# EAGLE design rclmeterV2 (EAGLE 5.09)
TP_SIGNAL_NAME: DUT-
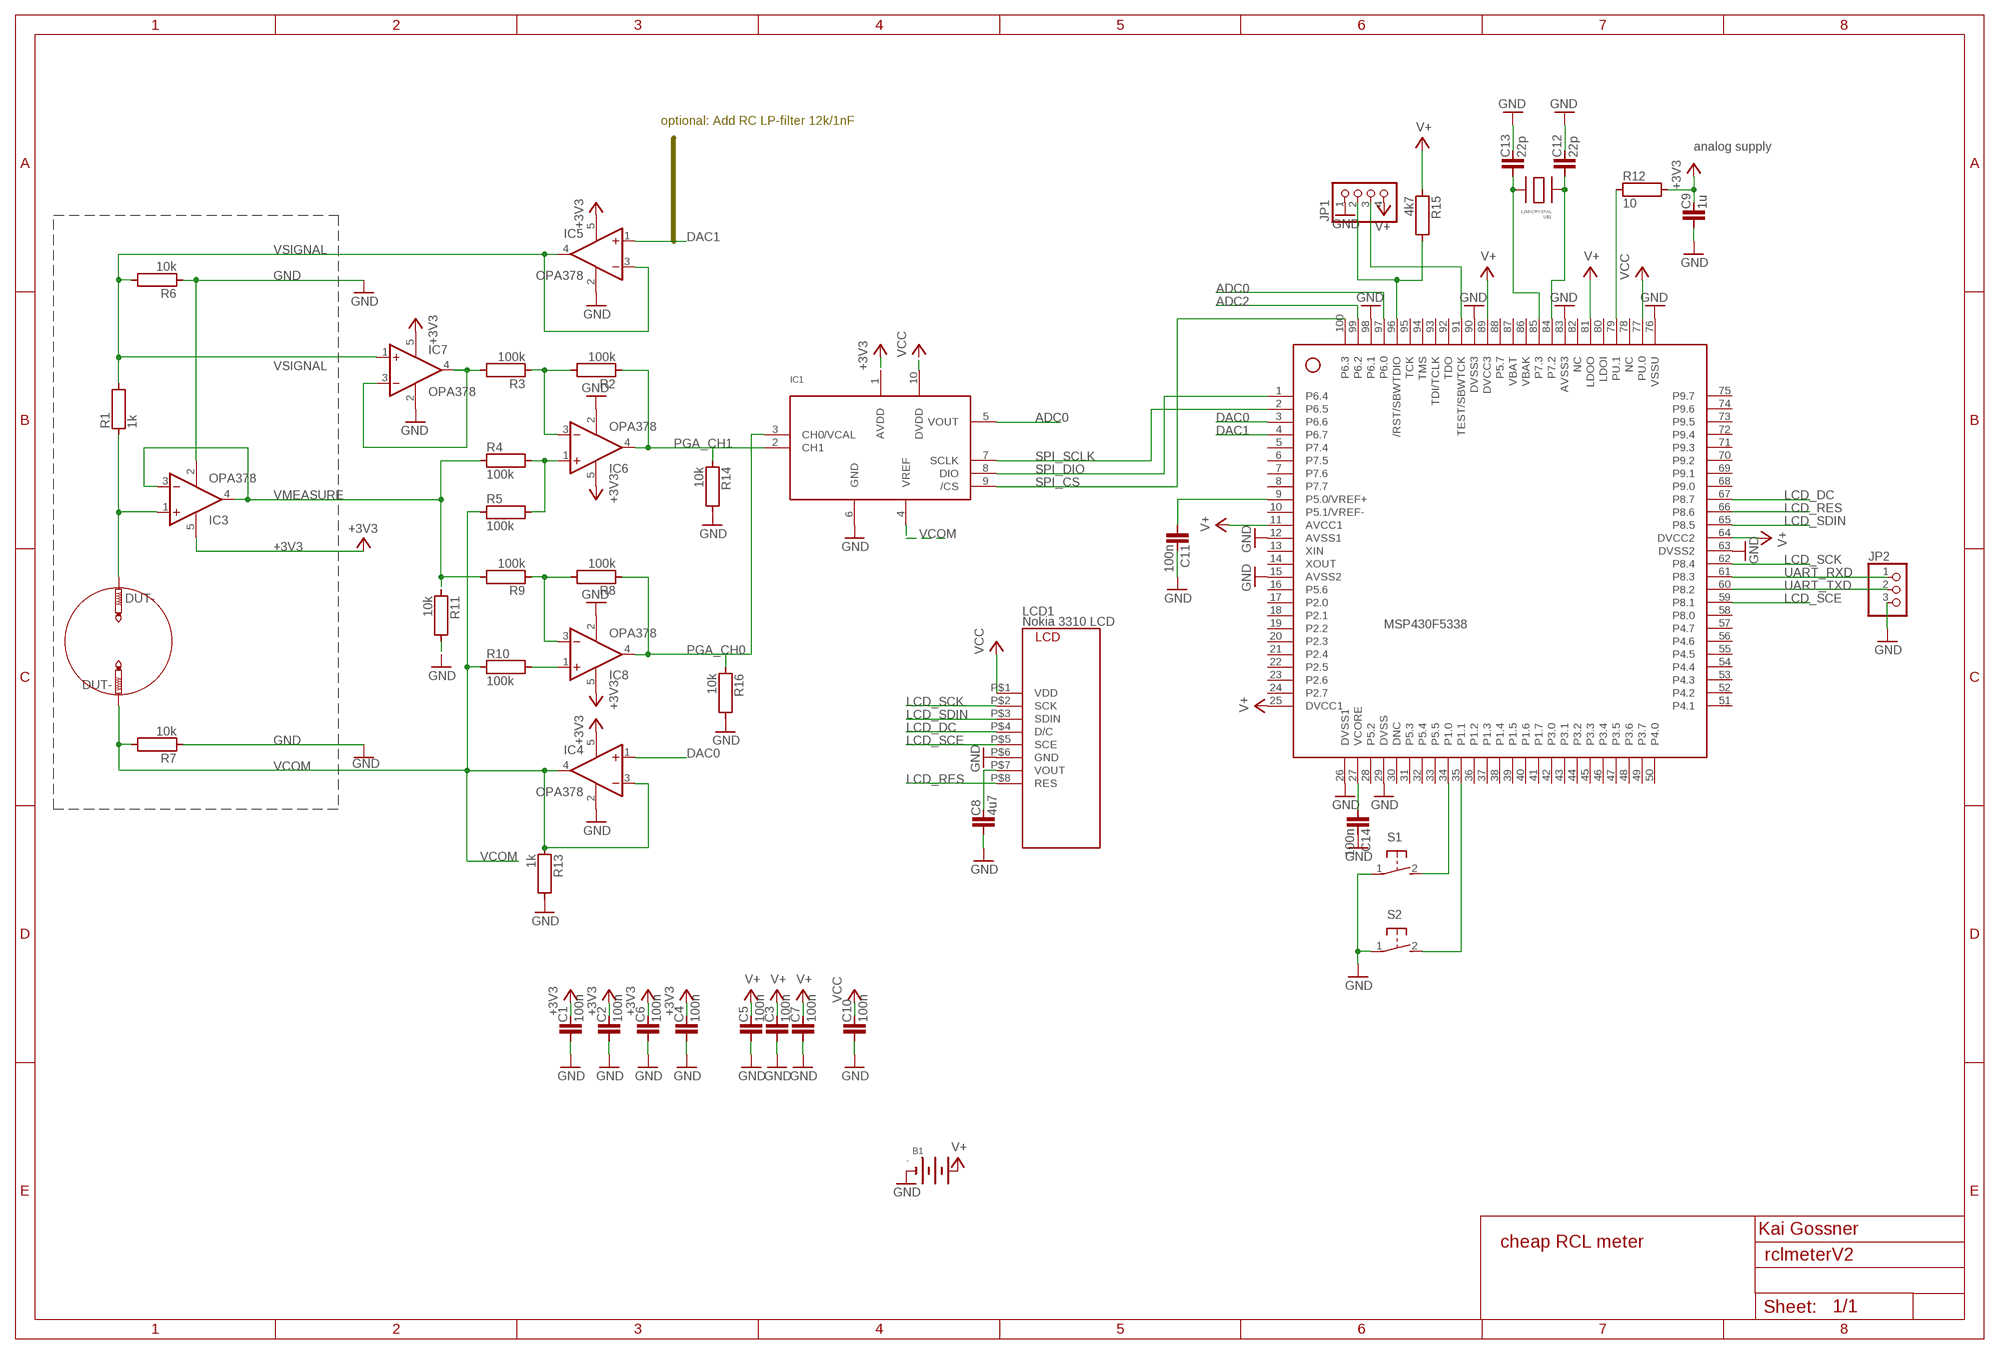
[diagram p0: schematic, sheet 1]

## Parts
B1  BATTERYCR2032  [CR2032]
C1  100n  C0603  [C0603]
C2  100n  C0603  [C0603]
C3  100n  C0603  [C0603]
C4  100n  C0603  [C0603]
C5  100n  C0603  [C0603]
C6  100n  C0603  [C0603]
C7  100n  C0603  [C0603]
C8  4u7  C0805  [C0805]
C9  1u  C0805  [C0805]
C10  100n  C0603  [C0603]
C11  100n  C0603  [C0603]
C12  22p  C0603  [C0603]
C13  22p  C0603  [C0603]
C14  100n  C0603  [C0603]
IC1  PGA113  [MSOP10_NO_TP]
IC2  F5338  [PZ100]
IC3  OPA378  [DCK_R-PDSO-G5]
IC4  OPA378  [DCK_R-PDSO-G5]
IC5  OPA378  [DCK_R-PDSO-G5]
IC6  OPA378  [DCK_R-PDSO-G5]
IC7  OPA378  [DCK_R-PDSO-G5]
IC8  OPA378  [DCK_R-PDSO-G5]
JP1  PINHD-1X4  [1X04]
JP2  PINHD-1X3  [1X03]
LCD1  NOKIA3310  [NOKIALCD]
R1  1k  R0603  [R0603]
R2  100k  R0603  [R0603]
R3  100k  R0603  [R0603]
R4  100k  R0603  [R0603]
R5  100k  R0603  [R0603]
R6  10k  R0603  [R0603]
R7  10k  R0603  [R0603]
R8  100k  R0603  [R0603]
R9  100k  R0603  [R0603]
R10  100k  R0603  [R0603]
R11  10k  R0603  [R0603]
R12  10  R0603  [R0603]
R13  1k  R0603  [R0603]
R14  10k  R0603  [R0603]
R15  4k7  R0603  [R0603]
R16  10k  R0603  [R0603]
S1  31-XX  [B3F-31XX]
S2  31-XX  [B3F-31XX]
TP1  DUT+  PTR1  [B0.6]
TP2  PTR1  [B0.6]
U$1  12M-CRYSTAL  7M-CRYSTAL  [XTAL3.2X2.5]

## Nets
+3V3: C1.2 C2.2 C4.2 C6.2 C9.2 IC1.1(AVDD) IC3.5(V+) IC4.5(V+) IC5.5(V+) IC6.5(V+) IC7.5(V+) IC8.5(V+) R12.2
ADC0: IC1.5(VOUT) IC2.97(P6.0)
ADC2: IC2.99(P6.2)
DAC0: IC2.3(P6.6) IC4.1(+IN)
DAC1: IC2.4(P6.7) IC5.1(+IN)
GND: B1.- C1.1 C2.1 C3.1 C4.1 C5.1 C6.1 C7.1 C8.1 C9.1 C10.1 C11.2 C12.2 C13.2 C14.2 IC1.6(GND) IC2.12(AVSS1) IC2.15(AVSS2) IC2.26(DVSS1) IC2.29(DVSS) IC2.63(DVSS2) IC2.76(VSSU) IC2.83(AVSS3) IC2.90(DVSS3) IC2.98(P6.1) IC3.2(V-) IC4.2(V-) IC5.2(V-) IC6.2(V-) IC7.2(V-) IC8.2(V-) JP1.1 JP2.3 LCD1.P$6(GND) R6.1 R7.1 R11.2 R13.2 R14.2 R16.2 S1.1(P) S2.1(P)
LCD_DC: IC2.67(P8.7) LCD1.P$4(D/C)
LCD_RES: IC2.66(P8.6) LCD1.P$8(RES)
LCD_SCE: IC2.59(P8.1) LCD1.P$5(SCE)
LCD_SCK: IC2.62(P8.4) LCD1.P$2(SCK)
LCD_SDIN: IC2.65(P8.5) LCD1.P$3(SDIN)
N$2: IC7.3(-IN) IC7.4(OUT) R3.2
N$3: C12.1 IC2.84(P7.2) U$1.2
N$4: IC3.1(+IN) R1.1 TP1.TP
N$5: C13.1 IC2.85(P7.3) U$1.4
N$6: IC8.1(+IN) R10.2
N$7: IC6.1(+IN) R4.2 R5.2
N$8: IC6.3(-IN) R2.2 R3.1
N$10: IC8.3(-IN) R8.2 R9.1
N$11: IC2.79(PU.1) R12.1
N$12: C11.1 IC2.9(P5.0/VREF+)
N$13: C8.2 LCD1.P$7(VOUT)
N$14: IC2.34(P1.0) S1.2(S)
N$15: IC2.35(P1.1) S2.2(S)
N$16: IC2.96(/RST/SBWTDIO) JP1.2 R15.2
N$17: IC2.91(TEST/SBWTCK) JP1.3
N$19: C14.1 IC2.27(VCORE)
PGA_CH0: IC1.3(CH0/VCAL) IC8.4(OUT) R8.1 R16.1
PGA_CH1: IC1.2(CH1) IC6.4(OUT) R2.1 R14.1
SPI_CS: IC1.9(/CS) IC2.100(P6.3)
SPI_DIO: IC1.8(DIO) IC2.1(P6.4)
SPI_SCLK: IC1.7(SCLK) IC2.2(P6.5)
UART_RXD: IC2.61(P8.3) JP2.1
UART_TXD: IC2.60(P8.2) JP2.2
V+: B1.+ C3.2 C5.2 C7.2 IC2.11(AVCC1) IC2.25(DVCC1) IC2.64(DVCC2) IC2.81(LDOO) IC2.89(DVCC3) JP1.4 R15.1
VCC: C10.2 IC1.10(DVDD) IC2.77(PU.0) LCD1.P$1(VDD)
VCOM: IC1.4(VREF) IC4.3(-IN) IC4.4(OUT) R5.1 R7.2 R10.1 R13.1 TP2.TP
VMEASURE: IC3.3(-IN) IC3.4(OUT) R4.1 R9.2 R11.1
VSIGNAL: IC5.3(-IN) IC5.4(OUT) IC7.1(+IN) R1.2 R6.2
Unconnected: IC2.5(P7.4) IC2.6(P7.5) IC2.7(P7.6) IC2.8(P7.7) IC2.10(P5.1/VREF-) IC2.13(XIN) IC2.14(XOUT) IC2.16(P5.6) IC2.17(P2.0) IC2.18(P2.1) IC2.19(P2.2) IC2.20(P2.3) IC2.21(P2.4) IC2.22(P2.5) IC2.23(P2.6) IC2.24(P2.7) IC2.28(P5.2) IC2.30(DNC) IC2.31(P5.3) IC2.32(P5.4) IC2.33(P5.5) IC2.36(P1.2) IC2.37(P1.3) IC2.38(P1.4) IC2.39(P1.5) IC2.40(P1.6) IC2.41(P1.7) IC2.42(P3.0) IC2.43(P3.1) IC2.44(P3.2) IC2.45(P3.3) IC2.46(P3.4) IC2.47(P3.5) IC2.48(P3.6) IC2.49(P3.7) IC2.50(P4.0) IC2.51(P4.1) IC2.52(P4.2) IC2.53(P4.3) IC2.54(P4.4) IC2.55(P4.5) IC2.56(P4.6) IC2.57(P4.7) IC2.58(P8.0) IC2.68(P9.0) IC2.69(P9.1) IC2.70(P9.2) IC2.71(P9.3) IC2.72(P9.4) IC2.73(P9.5) IC2.74(P9.6) IC2.75(P9.7) IC2.78(NC) IC2.80(LDOI) IC2.82(NC) IC2.86(VBAK) IC2.87(VBAT) IC2.88(P5.7) IC2.92(TDO) IC2.93(TDI/TCLK) IC2.94(TMS) IC2.95(TCK)

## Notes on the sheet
- optional: Add RC LP-filter 12k/1nF
- analog supply
- Nokia 3310 LCD | MSP430F5338
- Kai Gossner
- cheap RCL meter

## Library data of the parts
B1 = microbuilder:BATTERY
C1-C14 = KaiLib:C
IC1 = texas:PGA113
IC2 = TI_MSP430_v16:F5338
IC3-IC8 = texas:OPA378
JP1 = pinhead:PINHD-1X4: PIN HEADER
JP2 = pinhead:PINHD-1X3: PIN HEADER
LCD1 = KaiLib:NOKIA3310
R1-R16 = KaiLib:R
S1 S2 = switch-omron:31-XX: OMRON SWITCH
TP1 TP2 = testpad:PTR1: TEST PIN
U$1 = kg:7M-CRYSTAL

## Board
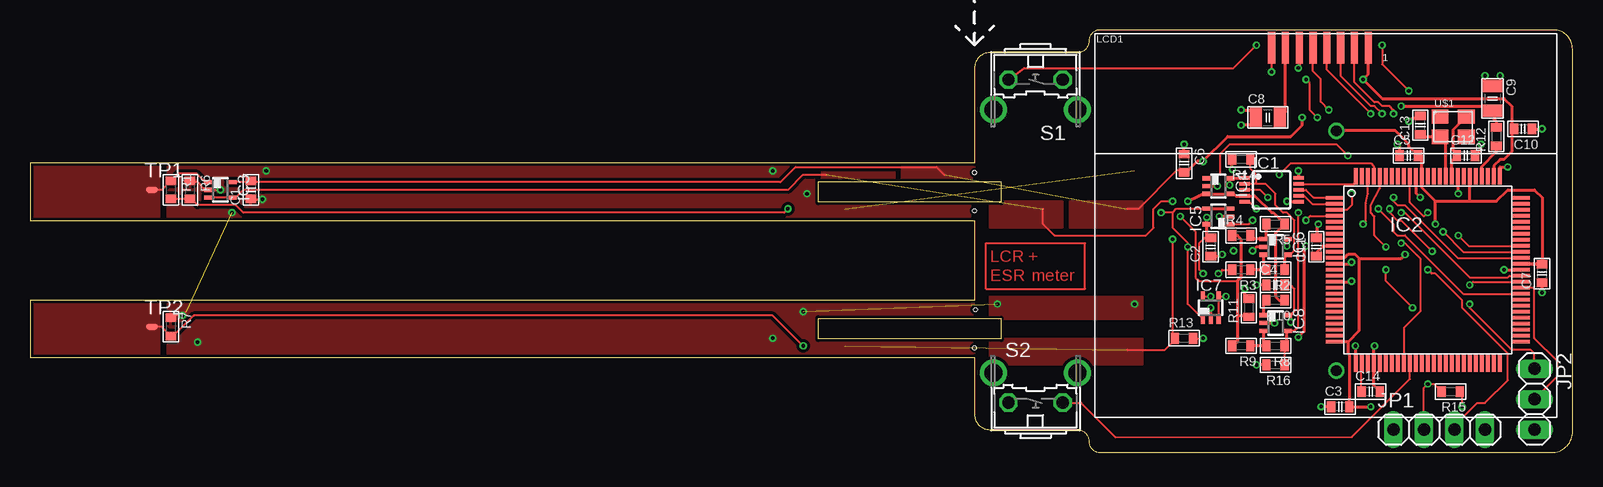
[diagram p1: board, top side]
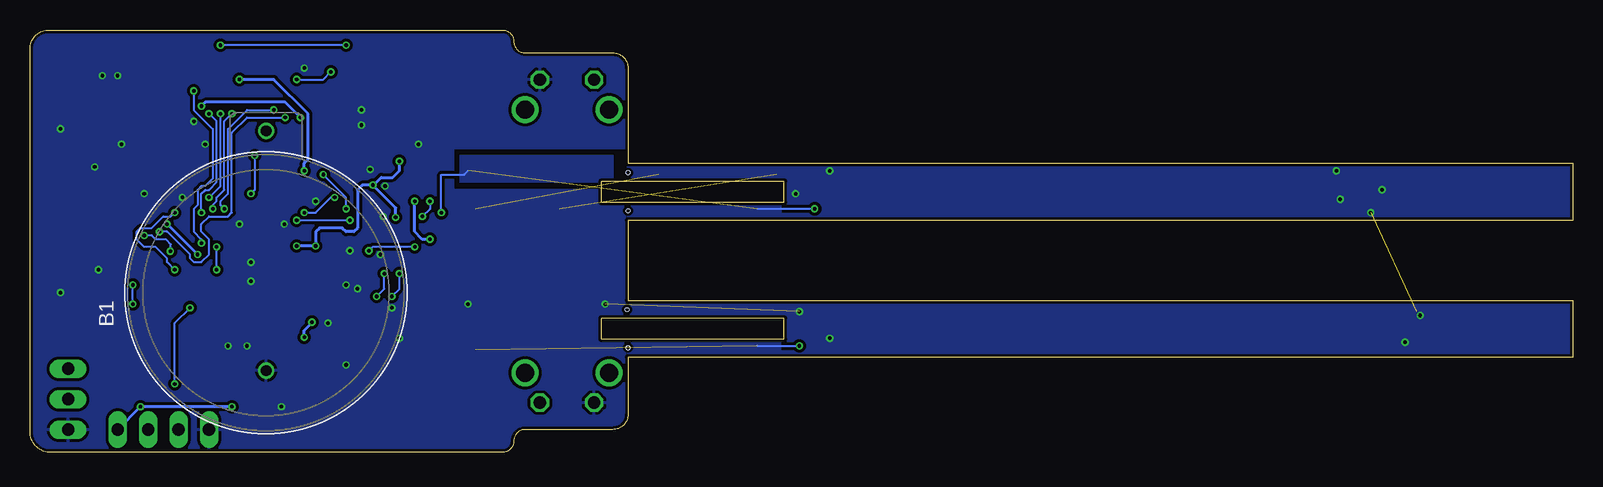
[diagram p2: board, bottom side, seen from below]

Size 128.59 x 35.25 mm. Coordinates in mm from the lower left corner, seen from the top.
Outline: 128.59,33.66 arc90 127,35.25 89.22,35.25 arc90 88.27,34.3 arc-90 87.31,33.34 80.01,33.34 arc90 78.74,32.07 78.74,24.14 0,24.14 0,19.37 78.74,19.37 78.74,12.71 0,12.71 0,7.94 78.74,7.94 78.74,3.18 arc90 80.01,1.91 87.31,1.91 arc-90 88.27,0.96 arc90 89.22,0.01 126.68,0.01 arc90 128.59,1.59 128.59,33.66
Outline: 65.72,20.89 65.72,22.62 80.96,22.62 80.96,20.89 65.72,20.89
Outline: 65.72,9.46 65.72,11.19 80.96,11.19 80.96,9.46 65.72,9.46
Copper layers (1*16): Top 0.035mm / dielectric 1.5mm / Bottom 0.035mm
Design rules "default *": minimum track width 5.5mil, minimum drill 0.25mm, track to track 5.5mil, track to pad 5.5mil, pad to pad 5.5mil, via to via 5.5mil, smd to smd 1mil, copper to edge 8mil, drill to drill 8mil, minimum pad ring 0.15mm, minimum via ring 0.15mm, stop-mask expansion 4mil, vias tented up to drill 0.35mm, thermal gap 10mil
Holes 0.3 mm at 78.74,23.34 78.82,11.91 78.74,20.17 78.74,8.74
tRestrict: 1 lines

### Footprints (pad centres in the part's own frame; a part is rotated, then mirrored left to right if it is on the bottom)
CR2032 = drill 0.9 round: + 10,0; - -10,0
C0603 = smd 0.7 x 0.9: 1 -0.762,0; 2 0.762,0
C0805 = smd 1 x 1.7: 1 -1.016,0; 2 1.016,0
MSOP10_NO_TP = smd 0.32 x 0.9: 1 -1,-2.25; 2 -0.5,-2.25; 3 0,-2.25; 4 0.5,-2.25; 5 1,-2.25; 6 1,2.25; 7 0.5,2.25; 8 0,2.25; 9 -0.5,2.25; 10 -1,2.25
PZ100 = smd 1.4 x 0.3: 1 -7.8,6; 2 -7.8,5.5; 3 -7.8,5; 4 -7.8,4.5; 5 -7.8,4; 6 -7.8,3.5; 7 -7.8,3; 8 -7.8,2.5; 9 -7.8,2; 10 -7.8,1.5; 11 -7.8,1; 12 -7.8,0.5; 13 -7.8,0; 14 -7.8,-0.5; 15 -7.8,-1; 16 -7.8,-1.5; 17 -7.8,-2; 18 -7.8,-2.5; 19 -7.8,-3; 20 -7.8,-3.5; 21 -7.8,-4; 22 -7.8,-4.5; 23 -7.8,-5; 24 -7.8,-5.5; 25 -7.8,-6; 51 7.8,-6; 52 7.8,-5.5; 53 7.8,-5; 54 7.8,-4.5; 55 7.8,-4; 56 7.8,-3.5; 57 7.8,-3; 58 7.8,-2.5; 59 7.8,-2; 60 7.8,-1.5; 61 7.8,-1; 62 7.8,-0.5; 63 7.8,0; 64 7.8,0.5; 65 7.8,1; 66 7.8,1.5; 67 7.8,2; 68 7.8,2.5; 69 7.8,3; 70 7.8,3.5; 71 7.8,4; 72 7.8,4.5; 73 7.8,5; 74 7.8,5.5; 75 7.8,6 | smd 0.3 x 1.4: 26 -6,-7.8; 27 -5.5,-7.8; 28 -5,-7.8; 29 -4.5,-7.8; 30 -4,-7.8; 31 -3.5,-7.8; 32 -3,-7.8; 33 -2.5,-7.8; 34 -2,-7.8; 35 -1.5,-7.8; 36 -1,-7.8; 37 -0.5,-7.8; 38 0,-7.8; 39 0.5,-7.8; 40 1,-7.8; 41 1.5,-7.8; 42 2,-7.8; 43 2.5,-7.8; 44 3,-7.8; 45 3.5,-7.8; 46 4,-7.8; 47 4.5,-7.8; 48 5,-7.8; 49 5.5,-7.8; 50 6,-7.8; 76 6,7.8; 77 5.5,7.8; 78 5,7.8; 79 4.5,7.8; 80 4,7.8; 81 3.5,7.8; 82 3,7.8; 83 2.5,7.8; 84 2,7.8; 85 1.5,7.8; 86 1,7.8; 87 0.5,7.8; 88 0,7.8; 89 -0.5,7.8; 90 -1,7.8; 91 -1.5,7.8; 92 -2,7.8; 93 -2.5,7.8; 94 -3,7.8; 95 -3.5,7.8; 96 -4,7.8; 97 -4.5,7.8; 98 -5,7.8; 99 -5.5,7.8; 100 -6,7.8
DCK_R-PDSO-G5 = smd 0.35 x 0.8: 1 -0.65,-0.95; 2 0,-0.95; 3 0.65,-0.95; 4 0.65,0.95; 5 -0.65,0.95
1X04 = drill 1.016 long: 1 -3.81,0; 2 -1.27,0; 3 1.27,0; 4 3.81,0
1X03 = drill 1.016 long: 1 -2.54,0; 2 0,0; 3 2.54,0
NOKIALCD = smd 0.6 x 2.65: P$1 8.05,-1.15; P$2 6.9,-1.15; P$3 5.75,-1.15; P$4 4.6,-1.15; P$5 3.45,-1.15; P$6 2.3,-1.15; P$7 1.15,-1.15; P$8 0,-1.15
R0603 = smd 0.7 x 0.9: 1 -0.762,0; 2 0.762,0
B3F-31XX = drill 1.016 octagon: 1 -2.261,-1.245; 2 2.261,-1.245 | drill 1.499 pad 2.159 round: 3 -3.505,1.245; 4 3.505,1.245
B0.6 = smd 1.016 x 0.508: TP 0,0
XTAL3.2X2.5 = smd 1.4 x 1.2: 1 0.7,2.3; 2 2.9,2.3; 3 2.9,0.6; 4 0.7,0.6

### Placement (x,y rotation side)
B1  108.9,16.83 90 bottom
C1  18.41,21.91 90 top
C2  98.42,17.15 90 top
C3  109.22,3.82 0 top
C4  103.82,13.98 0 top
C5  114.94,24.77 0 top
C6  96.2,24.14 270 top
C7  126.05,14.93 90 top
C8  103.19,27.95 0 top
C9  121.92,29.53 270 top
C10  124.46,26.99 180 top
C11  107.24,17.15 90 top
C12  119.7,24.77 0 top
C13  115.89,27.31 90 top
C14  111.76,5.09 0 top
IC1  103.5,21.91 270 top
IC2  116.52,15.25 0 top
IC3  15.88,21.91 270 top
IC4  99.06,22.23 270 top
IC5  99.06,19.69 90 top
IC6  103.82,17.15 270 top
IC7  98.42,12.07 0 top
IC8  103.82,10.8 270 top
JP1  117.47,1.91 0 top
JP2  125.41,4.45 270 top
LCD1  103.5,34.93 0 top
R1  11.75,21.91 270 top
R2  103.82,15.25 180 top
R3  100.97,15.25 180 top
R4  100.97,18.1 0 top
R5  103.82,19.06 180 top
R6  13.34,21.91 270 top
R7  11.75,10.48 270 top
R8  103.82,8.9 180 top
R9  100.97,8.9 180 top
R10  103.82,12.71 180 top
R11  101.6,12.07 90 top
R12  122.24,26.36 90 top
R13  96.2,9.53 0 top
R14  100.97,24.45 180 top
R15  118.43,5.09 180 top
R16  103.82,7.31 180 top
S1  83.82,29.85 180 top
S2  83.82,5.4 0 top
TP1  10.16,21.91 0 top
TP2  10.16,10.48 0 top
U$1  116.84,25.72 0 top

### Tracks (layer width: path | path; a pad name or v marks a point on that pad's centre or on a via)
+3V3  (via drill 0.3)  (1 unrouted)
  Top 0.155: IC3.5 17.13,22.56 17.14,22.55 18.41,22.55 | 104.47,11.45 IC8.5 105.11,11.45 105.41,11.75 105.41,13.66 105.09,13.98 C4.2 | 18.41,22.55 62.55,22.55 63.82,23.82 75.56,23.82 76.2,23.18 | 18.41,22.55 C1.2 | C6.2 96.2,23.5 95.57,23.5 92.39,20.33 91.44,20.33 | C2.2 97.92,17.91 97.47,17.47 97.47,15.25 v97.79,14.93 | v98.42,13.02 IC7.5
  Top 0.254: 105.11,11.45 105.09,11.44 v105.09,10.88 | IC1.1 101.22,22.88 IC4.5 v100.01,22.31 | v98.11,19.61 98.11,19.69 IC5.5 98.11,18.23 C2.2 | IC6.5 104.77,17.15 v104.78,17.23 | C6.2 96.65,23.63 97.31,24.3 v97.79,24.3 99.85,26.36 105.09,26.36 106.05,27.31 v106.05,27.95 | 122.06,28.18 122.06,27.81 122.24,27.63 R12.2 | 122.06,28.18 121.98,28.65 | v106.36,17.23 106.2,16.91 106.2,10.09 v105.73,9.61 | 122.06,28.18 122.06,28.52 C9.2 121.54,28.9 v114.3,28.9
  Bottom 0.155: v97.79,14.93 97.79,13.66 v98.42,13.02
  Bottom 0.254: v106.36,17.23 v104.78,17.23 104.78,18.42 104.46,18.74 102.55,18.74 102.23,18.42 101.6,18.42 101.28,18.74 101.28,21.91 100.89,22.31 v100.01,22.31 | v105.73,9.61 105.73,10.17 105.09,10.8 v105.09,10.88 | v98.11,19.61 98.11,20.41 v100.01,22.31 | v97.79,24.3 97.79,23.5 98.35,22.95 99.3,22.95 99.69,22.55 99.93,22.31 v100.01,22.31 | v114.3,28.9 113.98,29.22 107.31,29.22 v106.05,27.95
  pour Top (isolate 0.254): 72.71,22.55 72.71,24.14 78.74,24.14 78.74,22.55
  pour Top (isolate 0.254): 86.68,18.74 86.68,20.96 92.71,20.96 92.71,18.74
ADC0  (via drill 0.3)
  Top 0.155: IC1.5 101.65,20.91 v102.23,20.33 | v104.14,23.18 105.09,24.14 111.76,24.14 112.02,23.87 IC2.97
  Bottom 0.155: v102.23,20.33 102.23,21.28 v104.14,23.18
DAC0  (via drill 0.3)
  Top 0.155: IC4.1 98.76,22.88 99.22,23.34 99.22,24.93 100.01,25.72 108.9,25.72 v109.85,24.77 | v110.17,21.6 110.17,20.64 109.78,20.25 IC2.3
  Bottom 0.155: v109.85,24.77 109.85,21.91 v110.17,21.6
DAC1  (via drill 0.3)
  Top 0.155: IC5.1 101.59,19.04 v101.92,19.37 | 106.68,19.69 v106.36,19.37 106.73,19.75 IC2.4
  Bottom 0.155: v101.92,19.37 v106.36,19.37
GND  (via drill 0.3)  (2 unrouted)
  Top 0.155: v15.88,21.91 IC3.2 14.6,21.91 13.97,22.55 13.46,22.55 R6.1 | v19.37,21.12 18.45,21.12 C1.1 | R7.1 11.94,11.44 v12.7,11.44 13.02,11.75 | IC2.98 111.52,21.6 111.36,20.8 111.36,19.3 v111.12,19.06 | R13.2 v97.79,9.53
  Top 0.254: IC4.2 v98.98,22.23 | IC8.2 v103.74,10.8 | IC6.2 102.23,17.15 v101.92,16.83 | IC5.2 v99.14,19.69 | R11.2 101.41,13.02 101.28,13.02 v101.28,13.66 | IC2.90 115.52,21.64 v115.89,21.28 | IC2.83 119.02,21.64 v119.06,21.6 | v122.87,15.25 IC2.63 | IC2.12 110.04,15.75 v110.17,15.88 | IC2.15 110.12,14.25 v110.17,14.29 | IC2.26 110.52,8.86 v110.49,8.9 | v112.08,8.9 112.02,8.84 IC2.29 112.02,5.59 C14.2 | IC1.6 104.82,20.91 v104.78,20.96 | C4.1 v102.23,13.98 | C6.1 96.33,24.96 96.2,25.09 v96.2,25.72 | C2.1 99.25,16.39 v99.38,16.52 | v126.05,13.34 C7.1 | C9.1 122.3,30.55 122.56,30.8 v122.56,31.44 | 121.28,30.8 v121.28,31.44 | LCD1.P$6 105.81,32.15 v105.73,32.07 | C10.1 v126.05,26.99 | C11.2 107.31,18.1 107.31,18.98 v107.39,19.06 | C3.1 v107.63,3.82 | C13.2 115.06,27.76 v114.94,27.63 | C12.2 120.97,25.28 v120.97,25.72 | IC2.76 122.52,23.79 122.56,23.82 v123.19,23.82 | C5.1 114.17,25.53 v113.98,25.72 | IC7.2 v98.42,12.07 | C8.1 102.17,27.31 v100.97,27.31 | v100.97,28.58 101.92,28.58 101.92,27.95 | R14.2 100.2,23.64 v100.23,23.61 | R16.2 v102.23,7.31
  other vias: 64.77,21.6 64.45,11.75 61.91,9.53 13.97,9.21 16.83,20.01 61.91,23.5 19.69,23.5 92.08,12.39 80.64,12.39
  pour Bottom (isolate 0.254): 78.74,35.25 78.74,25.41 93.34,25.41 93.34,21.91 78.74,21.91 78.74,0.32 128.59,0.01 128.59,35.25
  pour Bottom (isolate 0.254): 0,24.3 0,19.37 78.74,19.37 78.74,24.3
  pour Bottom (isolate 0.254): 0,12.71 0,7.94 78.74,7.94 78.74,12.71
  pour Top (isolate 0.254): 11.43,24.14 11.43,19.37 78.74,19.37 78.74,20.96 65.41,20.96 65.41,24.14
  pour Top (isolate 0.254): 11.43,12.71 11.43,7.94 78.74,7.94 78.74,9.53 65.41,9.53 65.41,11.12 78.74,11.12 78.74,12.71
  pour Top: 80.01,11.12 80.01,13.02 92.71,13.02 92.71,11.12
LCD_DC  (via drill 0.3)
  Top 0.155: v116.89,16.79 114.3,19.37 113.98,19.37 113.35,20.01 v113.35,20.33 | v111.76,28.26 108.1,31.92 LCD1.P$4 | IC2.67 119.92,17.25 v119.06,18.1
  Bottom 0.155: v113.35,20.33 113.35,20.64 113.03,20.96 113.03,21.28 112.39,21.91 112.39,27.63 v111.76,28.26 | v116.89,16.79 116.84,16.83 116.84,17.37 117.25,17.79 118.11,17.79 118.43,18.1 v119.06,18.1
LCD_RES  (via drill 0.3)
  Top 0.155: v107.31,27.95 106.68,28.58 106.68,30.8 v106.36,31.12 | v103.5,31.76 LCD1.P$8 | IC2.66 119.47,16.75 v117.79,18.42
  Bottom 0.155: v107.31,27.95 110.49,27.95 111.76,26.68 111.76,20.01 112.08,19.69 113.66,19.69 114.3,19.06 114.3,18.42 113.66,17.79 113.66,16.52 114.3,15.88 114.94,15.88 115.25,16.2 115.25,16.52 117.16,18.42 v117.79,18.42 | v106.36,31.12 104.14,31.12 v103.5,31.76
LCD_SCE  (via drill 0.3)
  Top 0.155: IC2.59 119.47,13.25 114.62,18.1 113.98,18.1 113.66,18.42 113.66,19.06 v112.39,20.33 | v108.27,28.58 107.59,29.26 107.59,31.16 106.95,31.8 LCD1.P$5
  Bottom 0.155: v112.39,20.33 112.71,20.64 112.71,20.96 112.08,21.6 112.08,26.99 110.49,28.58 v108.27,28.58
LCD_SCK  (via drill 0.3)
  Top 0.155: IC2.62 123.33,14.75 123.19,14.61 120.02,14.61 114.62,20.01 v114.3,20.01 | v113.66,28.26 113.66,28.58 113.35,28.9 112.71,28.9 112.39,29.22 112.08,29.22 110.41,30.89 LCD1.P$2
  Bottom 0.155: v114.3,20.01 114.3,21.6 113.98,21.91 113.66,21.91 113.03,22.55 113.03,27.63 v113.66,28.26
LCD_SDIN  (via drill 0.3)
  Top 0.155: IC2.65 119.02,16.25 114.62,20.64 113.98,20.64 113.66,20.96 v113.66,21.28 | v112.71,28.26 112.08,28.9 111.76,28.9 109.25,31.4 LCD1.P$3
  Bottom 0.155: v113.66,21.28 112.71,22.23 v112.71,28.26
N$1
  Top 0.155: 79.69,13.66 79.69,17.47 87.95,17.47 87.95,13.66 79.69,13.66
N$2  (via drill 0.3)
  Top 0.155: IC7.3 IC7.4 v99.69,13.02 | R3.2 99.38,15.25 v99.06,14.93
  Bottom 0.155: v99.06,14.93 99.06,13.66 v99.69,13.02
N$3
  Top 0.254: IC2.84 118.52,24.36 C12.1 118.94,24.9 118.67,25.17 118.67,26.95 U$1.2
N$4
  Top 0.155: TP1.TP 10.99,21.91 R1.1 12.34,23.26 13.89,23.26 14.59,22.56 IC3.1
  pour Top (isolate 0.254, no thermals): 0,24.14 0,19.37 10.8,19.37 10.8,24.14
N$5
  Top 0.254: IC2.85 118.02,25.84 U$1.4 115.98,26.32 C13.1
N$6
  Top 0.254: IC8.1 102.87,12.52 R10.2
N$7
  Top 0.254: R5.2 103.06,17.99 IC6.1 102.06,17.8 R4.2
N$8
  Top 0.254: R3.1 R2.2 102.87,15.44 IC6.3
N$10
  Top 0.254: IC8.3 102.87,9.09 R8.2 R9.1
N$11
  Top 0.254: IC2.79 121.02,23.87 122.24,25.09 122.29,25.54 R12.1
N$12
  Top 0.254: IC2.9 107.81,17.25 107.08,16.52 C11.1
N$13
  Top 0.254: LCD1.P$7 104.66,28.4 C8.2
N$14  (via drill 0.3)
  Top 0.155: v112.71,33.98 112.71,32.39 v114.94,30.17 | v114.3,17.47 114.62,17.47 115.89,16.2 115.89,11.75 114.52,10.39 IC2.34 | v102.23,33.98 100.33,32.07 82.86,32.07 S1.2
  Bottom 0.155: v114.94,30.17 114.94,28.58 113.35,26.99 113.35,22.87 113.98,22.23 114.3,22.23 114.62,21.91 114.62,20.64 114.94,20.33 114.94,18.42 114.3,17.79 v114.3,17.47 | v102.23,33.98 v112.71,33.98
N$15
  Top 0.155: S2.2 87.61,4.16 90.49,1.28 110.2,1.3 115.02,6.13 IC2.35
N$16  (via drill 0.3)
  Top 0.155: IC2.96 112.52,22.04 111.76,20.64 111.76,20.01 112.08,19.69 112.08,18.1 v113.03,17.15 | v113.03,15.25 113.03,14.29 v115.25,12.07 | JP1.2 116.2,5.4 v116.52,5.72 117.03,5.72 R15.2
  Bottom 0.155: v113.03,15.25 v113.03,17.15 | v115.25,12.07 116.52,10.8 v116.52,5.72
N$17  (via drill 0.3)
  Top 0.155: IC2.91 115.02,20.87 116.2,19.69 v116.52,20.01 | v116.52,15.25 116.84,14.93 117.16,14.93 119.38,12.71 119.38,12.07 123.19,8.26 123.19,6.04 121.28,4.13 120.65,4.13 118.75,2.23 JP1.3
  Bottom 0.155: v116.52,20.01 116.84,19.69 117.47,19.69 118.43,18.74 119.38,18.74 119.7,18.42 119.7,17.79 119.06,17.15 118.11,17.15 117.16,16.2 117.16,15.88 v116.52,15.25
N$19
  Top 0.155: IC2.27 111,7.42 C14.1
PGA_CH0  (via drill 0.3)
  Top 0.155: IC1.3 102.55,21.91 v103.19,21.28 | v105.73,20.01 105.73,10.48 105.41,10.17 104.79,10.17 IC8.4 | R16.1 R8.1
  Top 0.254: IC8.4 104.77,9.09 R8.1
  Bottom 0.155: v103.19,21.28 103.5,21.28 104.78,20.01 v105.73,20.01
PGA_CH1
  Top 0.155: IC6.4 105.08,16.5 105.41,16.83 105.41,19.37 104.78,20.01 104.46,20.01 103.82,20.64 103.82,21.6 103,22.41 102.23,22.41 | 102.23,22.41 IC1.2 | R14.1 101.73,23.69 102.23,23.18 102.23,22.41
  Top 0.254: R2.1 104.58,16.31 IC6.4
SPI_CS
  Top 0.155: IC1.9 110.35,22.41 110.49,22.55 110.49,23.01 IC2.100
SPI_DIO
  Top 0.155: IC1.8 106.36,21.91 107,21.28 108.69,21.28 IC2.1
SPI_SCLK
  Top 0.155: IC2.2 106.89,20.75 106.23,21.41 IC1.7
UART_RXD  (via drill 0.3)
  Top 0.155: IC2.61 120.28,14.25 v120.02,13.98 | v120.02,12.39 120.02,12.07 123.51,8.58 125.09,8.58 125.41,8.26 JP2.1
  Bottom 0.155: v120.02,12.39 v120.02,13.98
UART_TXD
  Top 0.155: IC2.60 125.33,13.75 125.41,13.66 125.41,9.53 127.32,7.63 127.32,6.36 JP2.2
V+  (via drill 0.3)
  Top 0.155: R15.1 119.38,4.9 v119.38,3.82
  Top 0.254: IC2.81 120.02,20.97 120.02,20.96 | C7.2 125.99,15.75 IC2.64 125.91,15.75 126.05,15.88 126.05,21.28 125.41,21.91 123.19,21.91 122.24,20.96 120.02,20.96 | 117.16,20.96 120.02,20.96 | 109.89,9.25 IC2.25 | 109.89,9.25 110.81,10.17 110.81,16.2 | 110.81,16.2 110.49,16.52 109.85,16.52 109.59,16.25 IC2.11 | 117.16,20.96 116.02,22.1 IC2.89 116.02,24.72 C5.2 114.94,25.53 114.94,25.72 113.83,26.83 B1.+ | 110.81,16.2 114.3,16.2 v114.62,16.52 | v117.16,19.06 117.16,20.96 | v111.76,3.82 C3.2 110.01,5.06 110.01,8.1 109.89,8.23 109.89,9.25
  Bottom 0.254: v114.62,16.52 v117.16,19.06 | JP1.4 v119.38,3.82 v111.76,3.82
VCC  (via drill 0.3)
  Top 0.254: 123.61,26.99 123.51,26.99 123.51,25.09 122.87,24.45 122.56,24.45 122.02,23.92 IC2.77 | 123.61,26.99 123.61,27.21 123.51,27.31 123.51,28.9 122.87,29.53 112.71,29.53 v111.12,31.12 111.56,31.55 LCD1.P$1 | 123.61,26.99 C10.2 | IC1.10 105.75,23.47 v105.73,23.5
  Bottom 0.254: v105.73,23.5 105.73,24.14 105.41,24.45 105.41,28.26 108.27,31.12 v111.12,31.12
VCOM  (via drill 0.3)  (1 unrouted)
  Top 0.155: 11.87,9.85 12.06,9.85 13.65,11.44 61.91,11.44 v64.45,8.9 | R7.2 10.99,10.48 TP2.TP | 100.31,21.58 100.33,21.6 100.03,21.6 IC4.4 | 95.25,9.53 95.25,9.21 94.61,8.58 91.44,8.58 | 95.25,9.53 v95.25,17.79 | 95.25,9.53 R13.1
  Top 0.254: R10.1 104.58,12.58 104.33,12.58 104.14,12.71 103.82,13.02 103.82,18.29 R5.1 103.63,20.01 103.5,20.01 102.1,21.41 IC1.4 100.51,21.41 100.33,21.6 | 100.31,21.58 IC4.4 IC4.3 97.79,21.6 97.41,21.41 v96.52,20.96
  Top 0.406: 11.87,9.85 R7.2
  Bottom 0.155: 67.94,8.9 v64.45,8.9
  Bottom 0.254: v96.52,20.96 96.52,18.42 95.88,17.79 v95.25,17.79
  pour Bottom (isolate 0.254): 66.04,7.94 66.04,9.53 78.74,9.53 78.74,7.94
  pour Top (isolate 0.254, no thermals): 0,12.71 0,7.94 10.8,7.94 10.8,12.71
  pour Top (isolate 0.254): 80.01,7.31 80.01,9.53 92.71,9.53 92.71,7.31
VMEASURE  (via drill 0.3)  (1 unrouted)
  Top 0.155: IC3.3 IC3.4 17.13,21.26 17.78,21.91 63.18,21.91 64.45,23.18 66.36,23.18 | 100.65,14.29 97.47,14.29 97.16,14.61 97.16,18.42 v95.88,19.69 | v95.25,20.96 94.3,20.96 93.66,20.33 93.66,18.74 93.03,18.1 85.41,18.1 84.45,19.06 84.45,20.33
  Top 0.254: R4.1 100.65,18.1 100.97,17.79 100.97,14.61 100.65,14.29 100.65,11.44 | R9.2 100.33,8.9 100.65,9.21 100.65,11.44 | R11.1 101.47,11.44 100.65,11.44
  Bottom 0.155: v95.25,20.96 95.25,20.33 v95.88,19.69
  pour Top (isolate 0.254): 66.04,22.55 66.04,23.5 72.07,23.5 72.07,22.55
  pour Top (isolate 0.254): 80.01,18.74 80.01,20.96 86.04,20.96 86.04,18.74
VSIGNAL  (via drill 0.3)  (1 unrouted)
  Top 0.155: IC5.4 95.58,20.34 95.25,20.01 | 95.25,20.01 95.25,18.74 96.52,17.47 v96.52,17.15 96.52,12.39 97.78,11.13 IC7.1 | v100.33,16.83 100.2,16.71 | R1.2 R6.2 13.46,21.15 13.97,20.64 17.14,20.64 17.78,20.01 62.87,20.01 v63.18,20.33 | 95.25,20.01 v94.3,20.01
  Top 0.254: IC5.4 IC5.3
  Bottom 0.155: v100.33,16.83 100.01,17.15 v96.52,17.15 | v94.3,20.01 94.3,23.18 92.39,23.18 92.08,23.5 | v63.18,20.33 67.94,20.33
  pour Bottom (isolate 0.254): 66.04,20.96 66.04,19.37 78.74,19.37 78.74,20.96
  pour Bottom (isolate 0.254): 80.01,24.77 80.01,22.55 92.71,22.55 92.71,24.77

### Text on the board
Top: LCR | + | ESR | meter
tNames: Cut at this line
bStop: RX | C | D | 3V | TX
BD-Top: PGA_CH1 (current_sig) | pga_ch0 (voltage sig)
